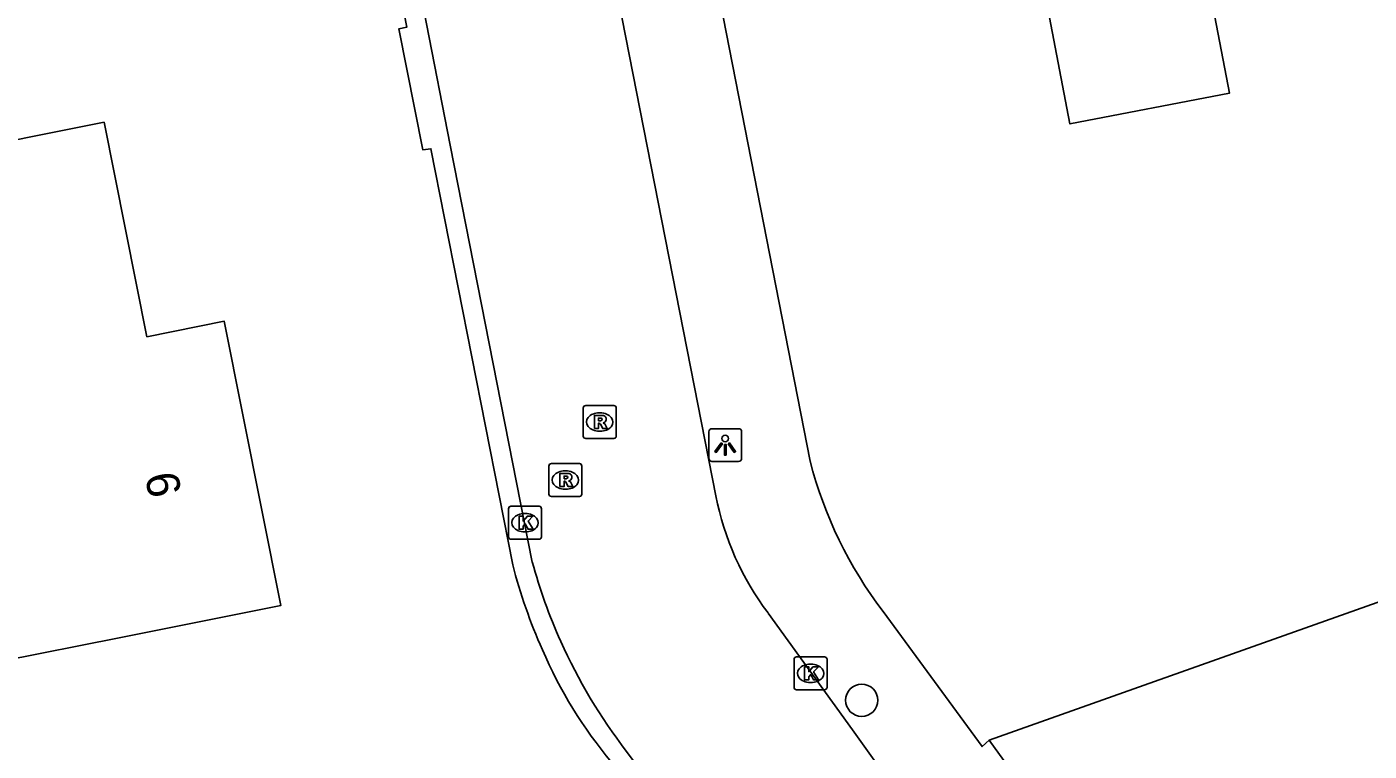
# Model space of a CAD drawing. Extents: x 157663 to 158496, y 379212 to 380934.
# Drawn here: x 158140.59 to 158181.33, y 380202.59 to 380224.57 of the extents above; entities that cross this region are included whole.
import ezdxf

# ---------------------------------------------------------------- set-up
doc = ezdxf.new("R2010")
doc.units = 0
for name, color, linetype in [('IMGEO_Boom', 7, 'Continuous'), ('IMGEO_Kolk', 7, 'Continuous'), ('IMGEO_Lichtpunt', 7, 'Continuous'), ('IMGEO_Pand', 7, 'Continuous'), ('IMGEO_Pand_nummerreeks', 7, 'Continuous'), ('IMGEO_Rijbaan_lokaal_open', 7, 'Continuous'), ('IMGEO_Rioolput', 7, 'Continuous'), ('IMGEO_Voetpad_open', 7, 'Continuous')]:
    doc.layers.add(name, color=color, linetype=linetype)

msp = doc.modelspace()

# ---------------------------------------------------------------- linework, layer by layer
at = {"layer": 'IMGEO_Boom'}
msp.add_circle((158165.929, 380204.131), 0.489, dxfattribs=at)
at = {"layer": 'IMGEO_Kolk'}
for p, q in [((158155.208, 380209.094), (158155.208, 380209.946)), ((158155.283, 380210.02), (158156.135, 380210.02)), ((158155.696, 380209.8), (158155.721, 380209.8)), ((158156.209, 380209.946), (158156.209, 380209.094)), ((158156.135, 380209.02), (158155.283, 380209.02)), ((158155.719, 380209.24), (158155.694, 380209.24)), ((158163.876, 380204.523), (158163.876, 380205.375)), ((158163.951, 380205.449), (158164.803, 380205.449)), ((158164.877, 380205.375), (158164.877, 380204.523)), ((158164.364, 380205.229), (158164.389, 380205.229)), ((158164.803, 380204.449), (158163.951, 380204.449)), ((158164.387, 380204.669), (158164.362, 380204.669))]:
    msp.add_line(p, q, dxfattribs=at)
for points in [[(158155.208, 380209.094), (158155.208, 380209.946)], [(158155.283, 380210.02), (158156.135, 380210.02)], [(158156.209, 380209.946), (158156.209, 380209.094)], [(158155.529, 380209.72), (158155.652, 380209.72), (158155.652, 380209.569), (158155.782, 380209.72), (158155.946, 380209.72), (158155.8, 380209.569), (158155.953, 380209.32), (158155.801, 380209.32), (158155.716, 380209.484), (158155.652, 380209.417), (158155.652, 380209.32), (158155.529, 380209.32), (158155.529, 380209.72)], [(158156.135, 380209.02), (158155.283, 380209.02)], [(158163.876, 380204.523), (158163.876, 380205.375)], [(158163.951, 380205.449), (158164.803, 380205.449)], [(158164.877, 380205.375), (158164.877, 380204.523)], [(158164.197, 380205.149), (158164.32, 380205.149), (158164.32, 380204.998), (158164.45, 380205.149), (158164.614, 380205.149), (158164.468, 380204.998), (158164.621, 380204.749), (158164.469, 380204.749), (158164.384, 380204.913), (158164.32, 380204.846), (158164.32, 380204.749), (158164.197, 380204.749), (158164.197, 380205.149)], [(158164.803, 380204.449), (158163.951, 380204.449)]]:
    msp.add_lwpolyline(points, dxfattribs=at)
for centre, start, end in [((158155.285, 380209.944), 91.552, 178.448), ((158155.285, 380209.944), 91.552, 178.448), ((158156.133, 380209.944), 1.552, 88.448), ((158156.133, 380209.944), 1.552, 88.448), ((158155.285, 380209.096), 181.552, 268.448), ((158155.285, 380209.096), 181.552, 268.448), ((158156.133, 380209.096), 271.552, 358.448), ((158156.133, 380209.096), 271.552, 358.448), ((158163.953, 380205.373), 91.552, 178.448), ((158163.953, 380205.373), 91.552, 178.448), ((158164.801, 380205.373), 1.552, 88.448), ((158164.801, 380205.373), 1.552, 88.448), ((158163.953, 380204.525), 181.552, 268.448), ((158163.953, 380204.525), 181.552, 268.448), ((158164.801, 380204.525), 271.552, 358.448), ((158164.801, 380204.525), 271.552, 358.448)]:
    msp.add_arc(centre, 0.0765, start, end, dxfattribs=at)
for centre, major_axis, ratio, start_param, end_param in [((158155.695, 380209.52), (-0.387, 0.002), 0.722429, 4.712389, 7.853982), ((158155.72, 380209.52), (-0.39, 0.002), 0.717154, 1.570796, 4.712389), ((158164.363, 380204.949), (-0.387, 0.002), 0.722429, 4.712389, 7.853982), ((158164.388, 380204.949), (-0.39, 0.002), 0.717154, 1.570796, 4.712389)]:
    msp.add_ellipse(centre, major_axis=major_axis, ratio=ratio, start_param=start_param, end_param=end_param, dxfattribs=at)
at = {"layer": 'IMGEO_Lichtpunt'}
for p, q in [((158161.288, 380212.279), (158161.288, 380211.472)), ((158161.288, 380212.279), (158161.288, 380211.472)), ((158162.19, 380212.374), (158161.382, 380212.374)), ((158162.19, 380212.374), (158161.382, 380212.374)), ((158162.284, 380211.472), (158162.284, 380212.279)), ((158162.284, 380211.472), (158162.284, 380212.279)), ((158161.382, 380211.378), (158162.19, 380211.378)), ((158161.382, 380211.378), (158162.19, 380211.378))]:
    msp.add_line(p, q, dxfattribs=at)
for points in [[(158161.662, 380211.943), (158161.701, 380211.915), (158161.513, 380211.653), (158161.475, 380211.68), (158161.662, 380211.943)], [(158161.764, 380211.895), (158161.811, 380211.895), (158161.811, 380211.573), (158161.764, 380211.573), (158161.764, 380211.895)], [(158161.874, 380211.915), (158161.912, 380211.942), (158162.099, 380211.68), (158162.06, 380211.652), (158161.874, 380211.915)]]:
    msp.add_lwpolyline(points, dxfattribs=at)
msp.add_circle((158161.787, 380212.077), 0.0994, dxfattribs=at)
for centre, start, end in [((158161.382, 380212.279), 90, 180), ((158161.382, 380212.279), 90, 180), ((158162.19, 380212.279), 0, 90), ((158162.19, 380212.279), 0, 90), ((158161.382, 380211.472), 180, 270), ((158161.382, 380211.472), 180, 270), ((158162.19, 380211.472), 270, 0), ((158162.19, 380211.472), 270, 360)]:
    msp.add_arc(centre, 0.0946, start, end, dxfattribs=at)
at = {"layer": 'IMGEO_Pand'}
for points in [[(158183.031, 380231.071), (158180.853, 380230.653), (158181.621, 380226.65), (158176.493, 380225.667), (158177.09, 380222.554), (158172.25, 380221.625), (158170.067, 380233.01), (158172.211, 380233.421), (158171.12, 380238.991), (158181.143, 380240.913), (158183.031, 380231.071)], [(158132.94, 380219.68), (158138.028, 380220.694), (158142.931, 380221.672), (158144.229, 380215.164), (158146.577, 380215.632), (158148.296, 380207.007), (158143.393, 380206.03), (158139.813, 380205.316), (158137.001, 380204.78), (158136.006, 380209.768), (158134.958, 380209.559), (158132.94, 380219.68)]]:
    msp.add_lwpolyline(points, dxfattribs=at)
at = {"layer": 'IMGEO_Rijbaan_lokaal_open'}
for points in [[(158161.502, 380210.338), (158157.34, 380231.523), (158156.436, 380236.131), (158146.416, 380287.415)], [(158140.788, 380285.896), (158141.818, 380280.546), (158142.979, 380274.611), (158148.242, 380247.584), (158149.491, 380241.169), (158152.719, 380224.655), (158153.44, 380220.98), (158155.93, 380208.328)], [(158169.797, 380202.917), (158190.532, 380210.271), (158193.686, 380211.088), (158245.234, 380221.247)], [(158170.91, 380195.875), (158165.649, 380203.239), (158163.088, 380206.78)], [(158173.283, 380198.101), (158169.797, 380202.917)], [(158158.783, 380202.588), (158160.925, 380199.75), (158162.134, 380198.138), (158165.292, 380193.972), (158166.001, 380192.931)]]:
    msp.add_lwpolyline(points, dxfattribs=at)
for centre, radius, start, end in [((158169.949, 380211.971), 8.603, 190.9405, 217.11), ((158171.955, 380212.71), 16.614, 195.2927, 204.1264), ((158172.002, 380212.745), 16.671, 204.1719, 217.5379)]:
    msp.add_arc(centre, radius, start, end, dxfattribs=at)
at = {"layer": 'IMGEO_Rioolput'}
for p, q in [((158157.476, 380212.15), (158157.476, 380213.002)), ((158157.551, 380213.076), (158158.403, 380213.076)), ((158158.477, 380213.002), (158158.477, 380212.15)), ((158157.964, 380212.856), (158157.989, 380212.856)), ((158157.987, 380212.296), (158157.962, 380212.296)), ((158158.403, 380212.076), (158157.551, 380212.076)), ((158156.433, 380210.389), (158156.433, 380211.241)), ((158156.508, 380211.315), (158157.36, 380211.315)), ((158156.921, 380211.095), (158156.946, 380211.095)), ((158157.434, 380211.241), (158157.434, 380210.389)), ((158157.36, 380210.315), (158156.508, 380210.315)), ((158156.944, 380210.535), (158156.919, 380210.535))]:
    msp.add_line(p, q, dxfattribs=at)
for points in [[(158157.476, 380212.15), (158157.476, 380213.002)], [(158157.551, 380213.076), (158158.403, 380213.076)], [(158158.477, 380213.002), (158158.477, 380212.15)], [(158158.065, 380212.774), (158157.813, 380212.776), (158157.813, 380212.376)], [(158157.991, 380212.695), (158157.937, 380212.695), (158157.937, 380212.614)], [(158157.937, 380212.614), (158157.989, 380212.614)], [(158157.813, 380212.376), (158157.937, 380212.376), (158157.937, 380212.538), (158157.948, 380212.538)], [(158157.995, 380212.509), (158158.066, 380212.376), (158158.206, 380212.376), (158158.141, 380212.502)], [(158158.403, 380212.076), (158157.551, 380212.076)], [(158156.433, 380210.389), (158156.433, 380211.241)], [(158156.508, 380211.315), (158157.36, 380211.315)], [(158157.022, 380211.013), (158156.77, 380211.015), (158156.77, 380210.615)], [(158157.434, 380211.241), (158157.434, 380210.389)], [(158156.77, 380210.615), (158156.894, 380210.615), (158156.894, 380210.777), (158156.905, 380210.777)], [(158156.948, 380210.934), (158156.894, 380210.934), (158156.894, 380210.853)], [(158156.894, 380210.853), (158156.946, 380210.853)], [(158156.952, 380210.748), (158157.023, 380210.615), (158157.163, 380210.615), (158157.098, 380210.741)], [(158157.36, 380210.315), (158156.508, 380210.315)]]:
    msp.add_lwpolyline(points, dxfattribs=at)
for centre, radius, start, end in [((158157.553, 380213), 0.0765, 91.552, 178.448), ((158157.553, 380213), 0.0765, 91.552, 178.448), ((158158.401, 380213), 0.0765, 1.552, 88.448), ((158158.401, 380213), 0.0765, 1.552, 88.448), ((158157.973, 380212.803), 0.19, 274.7715, 282.9687), ((158157.997, 380212.599), 0.0964, 77.0061, 93.1865), ((158158.011, 380212.656), 0.0378, 276.6634, 79.6772), ((158158.064, 380212.664), 0.109, 350.3612, 89.416), ((158158.062, 380212.664), 0.112, 277.5842, 350.9817), ((158157.947, 380212.485), 0.0533, 26.0293, 88.6989), ((158158.046, 380212.449), 0.108, 29.5134, 73.7905), ((158157.553, 380212.152), 0.0765, 181.552, 268.448), ((158157.553, 380212.152), 0.0765, 181.552, 268.448), ((158158.401, 380212.152), 0.0765, 271.552, 358.448), ((158158.401, 380212.152), 0.0765, 271.552, 358.448), ((158156.51, 380211.239), 0.0765, 91.552, 178.448), ((158156.51, 380211.239), 0.0765, 91.552, 178.448), ((158157.021, 380210.903), 0.109, 350.3612, 89.416), ((158157.358, 380211.239), 0.0765, 1.552, 88.448), ((158157.358, 380211.239), 0.0765, 1.552, 88.448), ((158156.904, 380210.724), 0.0533, 26.0293, 88.6989), ((158156.93, 380211.042), 0.19, 274.7715, 282.9687), ((158156.954, 380210.838), 0.0964, 77.0061, 93.1865), ((158156.968, 380210.895), 0.0378, 276.6634, 79.6772), ((158157.019, 380210.903), 0.112, 277.5842, 350.9817), ((158157.003, 380210.688), 0.108, 29.5134, 73.7905), ((158156.51, 380210.391), 0.0765, 181.552, 268.448), ((158156.51, 380210.391), 0.0765, 181.552, 268.448), ((158157.358, 380210.391), 0.0765, 271.552, 358.448), ((158157.358, 380210.391), 0.0765, 271.552, 358.448)]:
    msp.add_arc(centre, radius, start, end, dxfattribs=at)
for centre, major_axis, ratio, start_param, end_param in [((158157.963, 380212.576), (-0.387, 0.002), 0.722429, 4.712389, 7.853982), ((158157.988, 380212.576), (-0.39, 0.002), 0.717154, 1.570796, 4.712389), ((158156.92, 380210.815), (-0.387, 0.002), 0.722429, 4.712389, 7.853982), ((158156.945, 380210.815), (-0.39, 0.002), 0.717154, 1.570796, 4.712389)]:
    msp.add_ellipse(centre, major_axis=major_axis, ratio=ratio, start_param=start_param, end_param=end_param, dxfattribs=at)
at = {"layer": 'IMGEO_Voetpad_open'}
for points in [[(158149.807, 380286.831), (158149.852, 380285.801), (158151.156, 380278.824), (158164.365, 380211.386)], [(158155.336, 380208.246), (158152.854, 380220.868), (158152.603, 380220.841), (158151.881, 380224.509), (158152.119, 380224.558), (158142.387, 380274.463), (158141.254, 380280.411), (158141.375, 380280.459), (158140.296, 380285.582)], [(158166.582, 380206.823), (158169.582, 380202.726), (158169.797, 380202.917)]]:
    msp.add_lwpolyline(points, dxfattribs=at)
for centre, radius, start, end in [((158176.64, 380214.53), 12.671, 194.3655, 217.4614), ((158171.283, 380212.368), 16.472, 194.492, 204.0089), ((158168.419, 380210.819), 13.227, 202.9283, 220.3392)]:
    msp.add_arc(centre, radius, start, end, dxfattribs=at)

# ---------------------------------------------------------------- texts
at = {"layer": 'IMGEO_Pand_nummerreeks'}
msp.add_text('6', height=1, rotation=281.2699, dxfattribs=at).set_placement((158144.165, 380210.949))

doc.saveas('drawing.dxf')
